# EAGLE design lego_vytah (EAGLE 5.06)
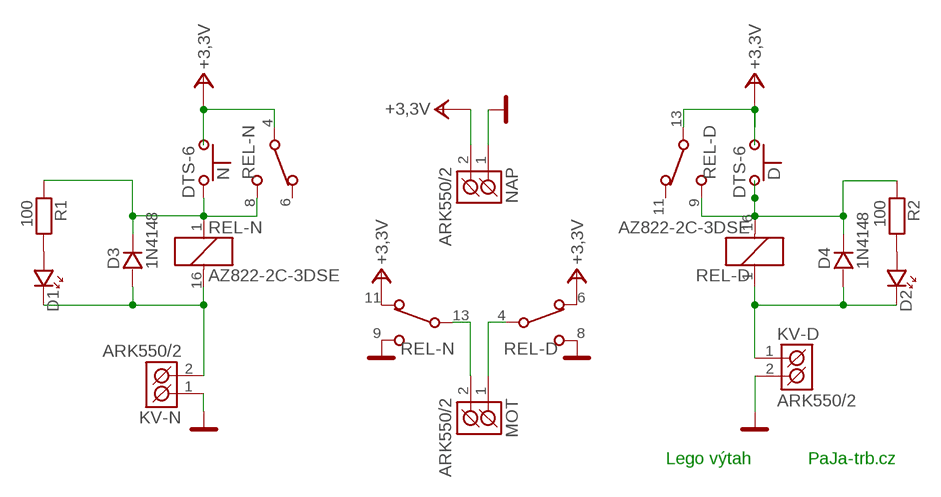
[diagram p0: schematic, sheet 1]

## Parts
D  DTS-6  [DTS-6]
D1  LED_TROJ  [LED_TROJ]
D2  LED_TROJ  [LED_TROJ]
D3  1N4148  1N4148.  [SOD-80]
D4  1N4148  1N4148.  [SOD-80]
KV-D  ARK550/2  [ARK550/2]
KV-N  ARK550/2  [ARK550/2]
MOT  ARK550/2  [ARK550/2]
N  DTS-6  [DTS-6]
NAP  ARK550/2  [ARK550/2]
R1  100  R_0805  [0805]
R2  100  R_0805  [0805]
REL-D  AZ822-2C-3DSE  RELE_G5V2  [REL_G5V2]
REL-N  AZ822-2C-3DSE  RELE_G5V2  [REL_G5V2]

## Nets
+3,3V: D.1 D.2(1A) N.1 N.2(1A) NAP.2(K2) REL-D.6(A:NC) REL-D.13(B:COM) REL-N.4(A:COM) REL-N.11(B:NC)
GND: KV-D.2(K2) KV-N.1(K1) NAP.1(K1) REL-D.8(A:NO) REL-N.9(B:NO)
N$1: D3.K N.3 R1.1 REL-N.1(RE:C1) REL-N.8(A:NO)
N$2: MOT.2(K2) REL-N.13(B:COM)
N$3: MOT.1(K1) REL-D.4(A:COM)
N$4: D4.K D.3 D.4(2A) R2.1 REL-D.9(B:NO) REL-D.16(RE:C2)
N$5: D1.K D3.A KV-N.2(K2) REL-N.16(RE:C2)
N$6: D2.K D4.A KV-D.1(K1) REL-D.1(RE:C1)
N$7: D1.A R1.2
N$8: D2.A R2.2
Unconnected: N.4(2A) REL-D.11(B:NC) REL-N.6(A:NC)

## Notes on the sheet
- Lego výtah | PaJa-trb.cz

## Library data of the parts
D N = #PaJa_prepinace:DTS?6: &micro;-tlacitko
D1 D2 = #PaJa_32:LED: LED - jednobarevna
D3 D4 = #PaJa_32:1N4148: Univerzalni dioda - 0,15A, 75V
KV-D KV-N MOT NAP = #PaJa_konektory:ARK550/2: Svorkovnice - roztec 3,5mm - dvojita
R1 R2 = #PaJa_32:R: Rezistor
REL-D REL-N = #PaJa_32:RELE_G5V2: RELE - 2x prepinaci, 5V, 12V, 24V max. spinany proud = 2A

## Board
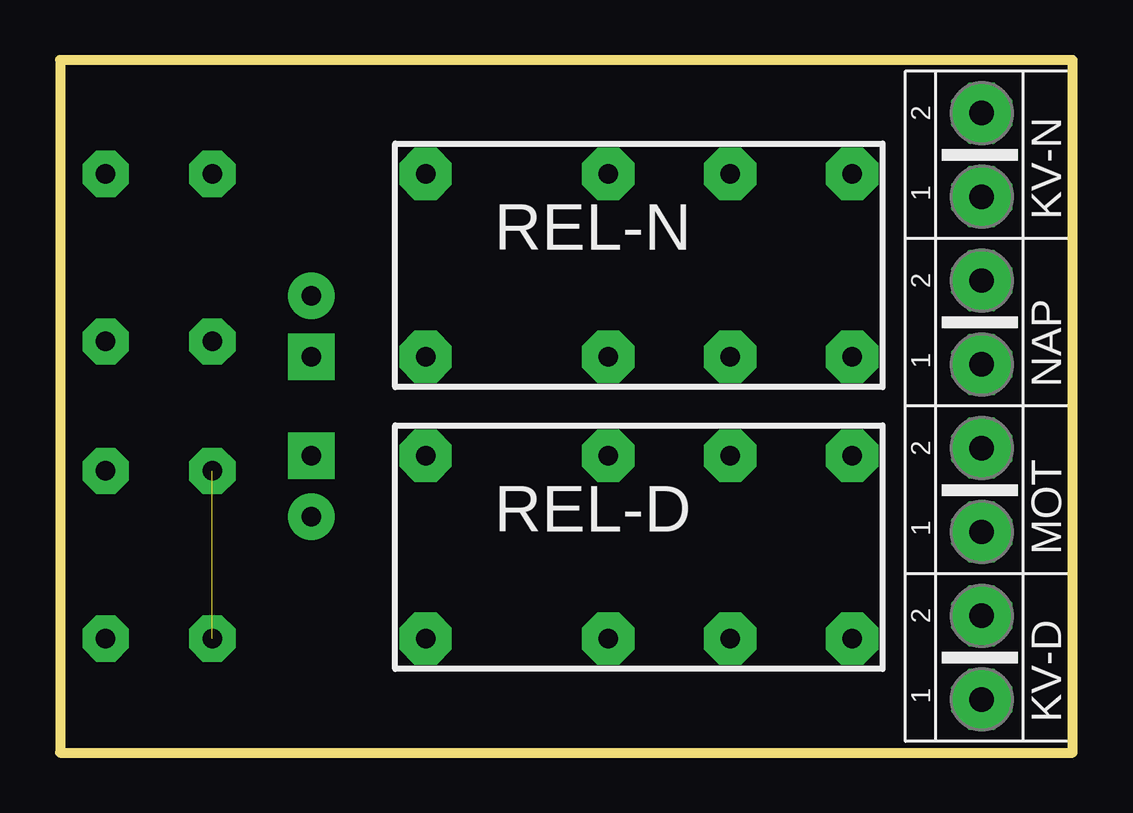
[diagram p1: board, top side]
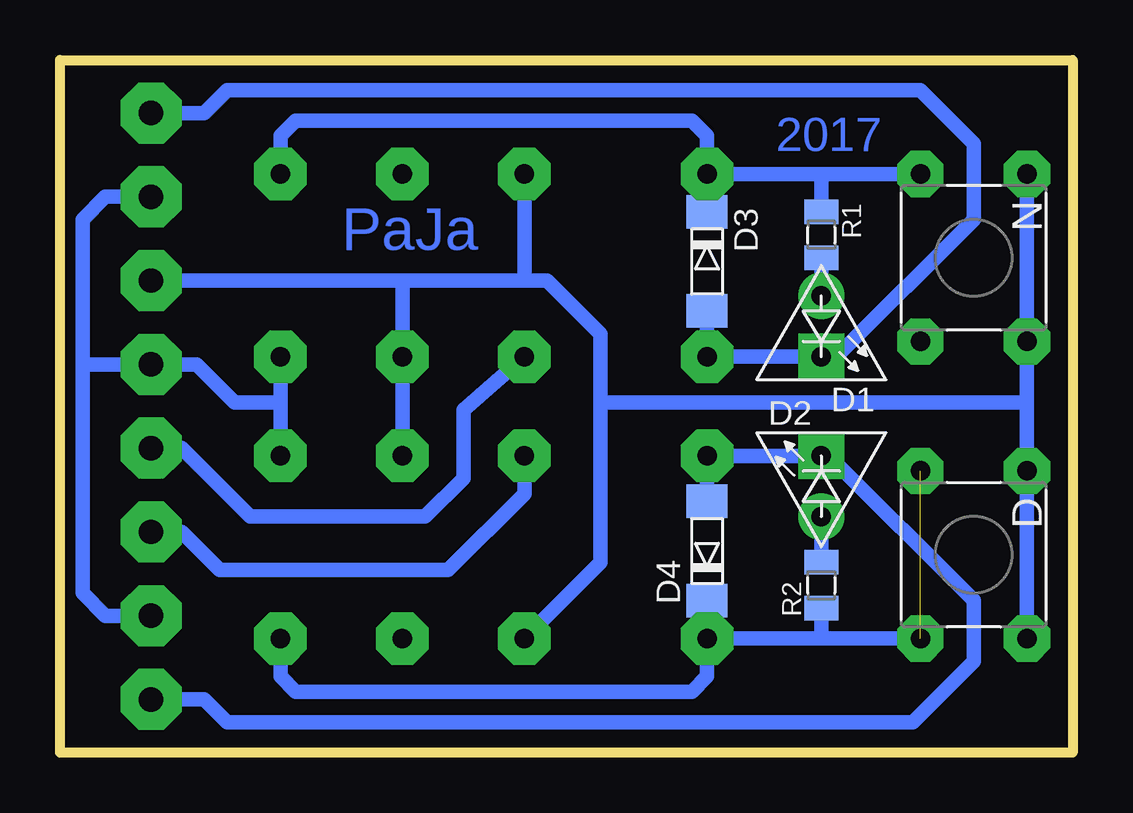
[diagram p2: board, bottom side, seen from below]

Size 42.22 x 28.88 mm. Coordinates in mm from the lower left corner, seen from the top.
Outline: 0,0 42.22,0 42.22,28.88 0,28.88 0,0
Copper layers (1*16): Top 0.035mm / dielectric 1.5mm / Bottom 0.035mm
Design rules "default": minimum track width 10mil, minimum drill 24mil, track to track 8mil, track to pad 8mil, pad to pad 8mil, via to via 8mil, smd to smd 8mil, copper to edge 40mil, drill to drill 8mil, minimum pad ring 10mil, minimum via ring 8mil, stop-mask expansion 4mil, vias tented up to drill 0mil, thermal gap 10mil

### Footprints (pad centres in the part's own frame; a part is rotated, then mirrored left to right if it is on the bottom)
DTS-6 = drill 0.813 pad 1.93 octagon: 1 -3.493,2.223; 2 3.493,2.223; 3 -3.493,-2.223; 4 3.493,-2.223
LED_TROJ = drill 0.813 pad 1.93 round: A -2.54,0 | drill 0.813 pad 1.93 square: K 0,0
SOD-80 = smd 1.397 x 1.702: A 1.905,0; K -2.223,0
ARK550/2 = drill 1.016 pad 2.54 octagon: 1 0,0; 2 3.493,0
0805 = smd 1.016 x 1.422: 1 -0.953,0; 2 0.953,0
REL_G5V2 = drill 0.813 pad 2.184 octagon: 1 -8.89,3.81; 4 -1.27,3.81; 6 3.81,3.81; 8 8.89,3.81; 9 8.89,-3.81; 11 3.81,-3.81; 13 -1.27,-3.81; 16 -8.89,-3.81

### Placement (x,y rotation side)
D  4.13,8.26 270 bottom
D1  10.48,16.51 270 bottom
D2  10.48,12.38 90 bottom
D3  15.24,20.32 270 bottom
D4  15.24,8.57 90 bottom
KV-D  38.42,2.22 90 top
KV-N  38.42,23.18 90 top
MOT  38.42,9.21 90 top
N  4.13,20.64 270 bottom
NAP  38.42,16.19 90 top
R1  10.48,21.59 270 bottom
R2  10.48,6.99 90 bottom
REL-D  24.13,8.57 0 top
REL-N  24.13,20.32 0 top

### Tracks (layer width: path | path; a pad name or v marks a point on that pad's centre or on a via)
+3,3V
  Bottom 0.61: 1.91,14.61 19.68,14.61 | 19.68,14.61 19.68,7.94 REL-D.13 | REL-D.6 REL-N.11 27.94,19.68 | 22.86,19.68 REL-N.4 | 22.86,19.68 27.94,19.68 | 27.94,19.68 NAP.2 | 22.86,19.68 21.91,19.68 19.68,17.46 19.68,14.61 | N.1 N.2 1.91,14.61 | 1.91,14.61 D.1 D.2
GND
  Bottom 0.61: 33.02,14.61 REL-D.8 | 33.02,14.61 REL-N.9 | 41.27,16.19 NAP.1 36.51,16.19 34.92,14.61 33.02,14.61 | 41.27,16.19 41.27,22.23 40.32,23.18 KV-N.1 | 41.27,16.19 41.27,6.67 40.32,5.71 KV-D.2
N$1
  Bottom 0.61: REL-N.1 D3.K | REL-N.8 33.02,25.72 32.38,26.35 15.88,26.35 15.24,25.72 REL-N.1 | 10.48,24.13 REL-N.1 | R1.1 10.48,24.13 | 10.48,24.13 N.3
N$2
  Bottom 0.61: MOT.2 37.15,12.7 34.29,9.84 26.99,9.84 25.4,11.43 25.4,14.29 REL-N.13
N$3
  Bottom 0.61: REL-D.4 22.86,10.79 26.04,7.62 35.56,7.62 37.15,9.21 MOT.1
N$4  (1 unrouted)
  Bottom 0.61: REL-D.16 D4.K | REL-D.16 15.24,3.17 15.88,2.54 32.38,2.54 33.02,3.17 REL-D.9 | 10.48,4.76 REL-D.16 | 10.48,4.76 R2.1 | D.4 10.48,4.76
N$5
  Bottom 0.61: D3.A REL-N.16 D1.K 9.84,16.51 4.13,22.23 4.13,25.4 6.35,27.62 35.24,27.62 36.2,26.67 KV-N.2
N$6
  Bottom 0.61: D4.A REL-D.1 D2.K 10.16,12.38 4.13,6.35 4.13,3.81 6.67,1.27 35.24,1.27 36.2,2.22 KV-D.1
N$7
  Bottom 0.61: D1.A R1.2
N$8
  Bottom 0.61: R2.2 D2.A

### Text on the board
Bottom: 2017 | PaJa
